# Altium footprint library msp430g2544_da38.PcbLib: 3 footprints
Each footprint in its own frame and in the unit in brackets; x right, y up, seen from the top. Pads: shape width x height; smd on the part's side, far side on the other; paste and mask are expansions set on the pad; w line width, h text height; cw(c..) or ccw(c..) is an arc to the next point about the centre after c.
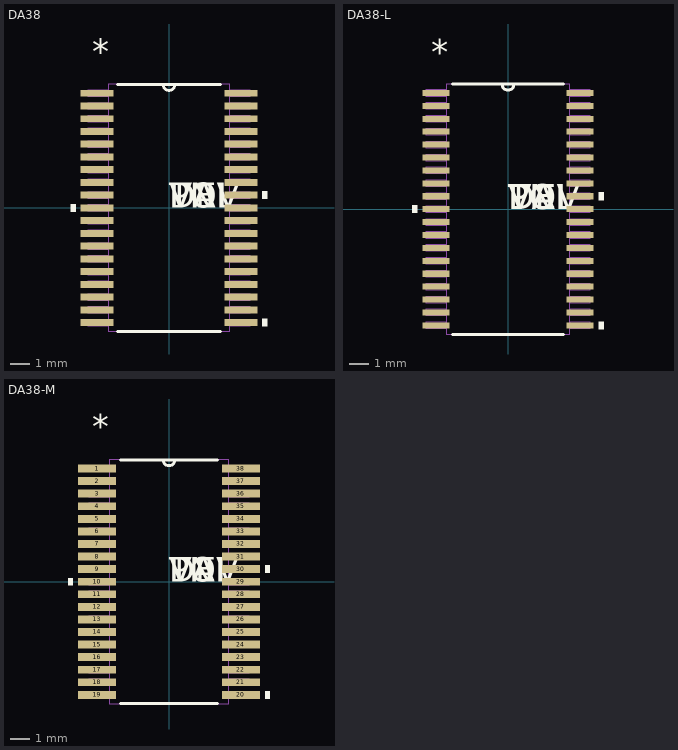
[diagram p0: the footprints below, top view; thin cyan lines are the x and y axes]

## DA38 [mil]
pads (38):
  rect 66x14 smd: 1(-144.5,230.31) 2(-144.5,204.72) 3(-144.5,179.13) 4(-144.5,153.54) 5(-144.5,127.95) 6(-144.5,102.36) 7(-144.5,76.77) 8(-144.5,51.18) 9(-144.5,25.59) 10(-144.5,0) 11(-144.5,-25.59) 12(-144.5,-51.18) 13(-144.5,-76.77) 14(-144.5,-102.36) 15(-144.5,-127.95) 16(-144.5,-153.54) 17(-144.5,-179.13) 18(-144.5,-204.72) 19(-144.5,-230.31) 20(144.5,-230.31) 21(144.5,-204.72) 22(144.5,-179.13) 23(144.5,-153.54) 24(144.5,-127.95) 25(144.5,-102.36) 26(144.5,-76.77) 27(144.5,-51.18) 28(144.5,-25.59) 29(144.5,0) 30(144.5,25.59) 31(144.5,51.18) 32(144.5,76.77) 33(144.5,102.36) 34(144.5,127.95) 35(144.5,153.54) 36(144.5,179.13) 37(144.5,204.72) 38(144.5,230.31)
Top Overlay:
  region: -187.5,7.5 -197.5,7.5 -197.5,-7.5 -187.5,-7.5
  region: 187.5,-222.81 197.5,-222.81 197.5,-237.81 187.5,-237.81
  region: 187.5,33.09 197.5,33.09 197.5,18.09 187.5,18.09
  lines w6: -103.92,-248 103.92,-248 ; -103.92,248 103.92,248 ; -12,248 ccw(c0,248) 12,248
  text "*" at -154.5,289.31 h50
  text "PN" at 0,0 h50
  text "DEV" at 0,0 h50
  text "VAL" at 0,0 h50
  text "TOL" at 0,0 h50
Mechanical 1:
  drawing of 157 lines, arcs and shapes, not listed
  text "*" at -154.5,289.31 h50
  text "RefDes2" at 0,0 h50

## DA38-L [mil]
pads (38):
  rect 54x12 smd: 1(-142.5,230.31) 2(-142.5,204.72) 3(-142.5,179.13) 4(-142.5,153.54) 5(-142.5,127.95) 6(-142.5,102.36) 7(-142.5,76.77) 8(-142.5,51.18) 9(-142.5,25.59) 10(-142.5,0) 11(-142.5,-25.59) 12(-142.5,-51.18) 13(-142.5,-76.77) 14(-142.5,-102.36) 15(-142.5,-127.95) 16(-142.5,-153.54) 17(-142.5,-179.13) 18(-142.5,-204.72) 19(-142.5,-230.31) 20(142.5,-230.31) 21(142.5,-204.72) 22(142.5,-179.13) 23(142.5,-153.54) 24(142.5,-127.95) 25(142.5,-102.36) 26(142.5,-76.77) 27(142.5,-51.18) 28(142.5,-25.59) 29(142.5,0) 30(142.5,25.59) 31(142.5,51.18) 32(142.5,76.77) 33(142.5,102.36) 34(142.5,127.95) 35(142.5,153.54) 36(142.5,179.13) 37(142.5,204.72) 38(142.5,230.31)
Top Overlay:
  region: -179.5,7.5 -189.5,7.5 -189.5,-7.5 -179.5,-7.5
  region: 179.5,-222.81 189.5,-222.81 189.5,-237.81 179.5,-237.81
  region: 179.5,33.09 189.5,33.09 189.5,18.09 179.5,18.09
  lines w6: -109.58,-248 109.58,-248 ; -109.58,248 109.58,248 ; -12,248 ccw(c0,248) 12,248
  text "*" at -152.5,287.31 h50
  text "PN" at 0,0 h50
  text "DEV" at 0,0 h50
  text "VAL" at 0,0 h50
  text "TOL" at 0,0 h50
Mechanical 1:
  drawing of 157 lines, arcs and shapes, not listed
  text "*" at -152.5,287.31 h50
  text "RefDes2" at 0,0 h50

## DA38-M [mil]
pads (38):
  rect 78x16 smd: 1(-146.5,230.31) 2(-146.5,204.72) 3(-146.5,179.13) 4(-146.5,153.54) 5(-146.5,127.95) 6(-146.5,102.36) 7(-146.5,76.77) 8(-146.5,51.18) 9(-146.5,25.59) 10(-146.5,0) 11(-146.5,-25.59) 12(-146.5,-51.18) 13(-146.5,-76.77) 14(-146.5,-102.36) 15(-146.5,-127.95) 16(-146.5,-153.54) 17(-146.5,-179.13) 18(-146.5,-204.72) 19(-146.5,-230.31) 20(146.5,-230.31) 21(146.5,-204.72) 22(146.5,-179.13) 23(146.5,-153.54) 24(146.5,-127.95) 25(146.5,-102.36) 26(146.5,-76.77) 27(146.5,-51.18) 28(146.5,-25.59) 29(146.5,0) 30(146.5,25.59) 31(146.5,51.18) 32(146.5,76.77) 33(146.5,102.36) 34(146.5,127.95) 35(146.5,153.54) 36(146.5,179.13) 37(146.5,204.72) 38(146.5,230.31)
Top Overlay:
  region: -195.5,7.5 -205.5,7.5 -205.5,-7.5 -195.5,-7.5
  region: 195.5,-222.81 205.5,-222.81 205.5,-237.81 195.5,-237.81
  region: 195.5,33.09 205.5,33.09 205.5,18.09 195.5,18.09
  lines w6: -98.68,-248 98.68,-248 ; -98.68,248 98.68,248 ; -12,248 ccw(c0,248) 12,248
  text "*" at -156.5,291.31 h50
  text "PN" at 0,0 h50
  text "DEV" at 0,0 h50
  text "VAL" at 0,0 h50
  text "TOL" at 0,0 h50
Mechanical 1:
  drawing of 157 lines, arcs and shapes, not listed
  text "*" at -156.5,291.31 h50
  text "RefDes2" at 0,0 h50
